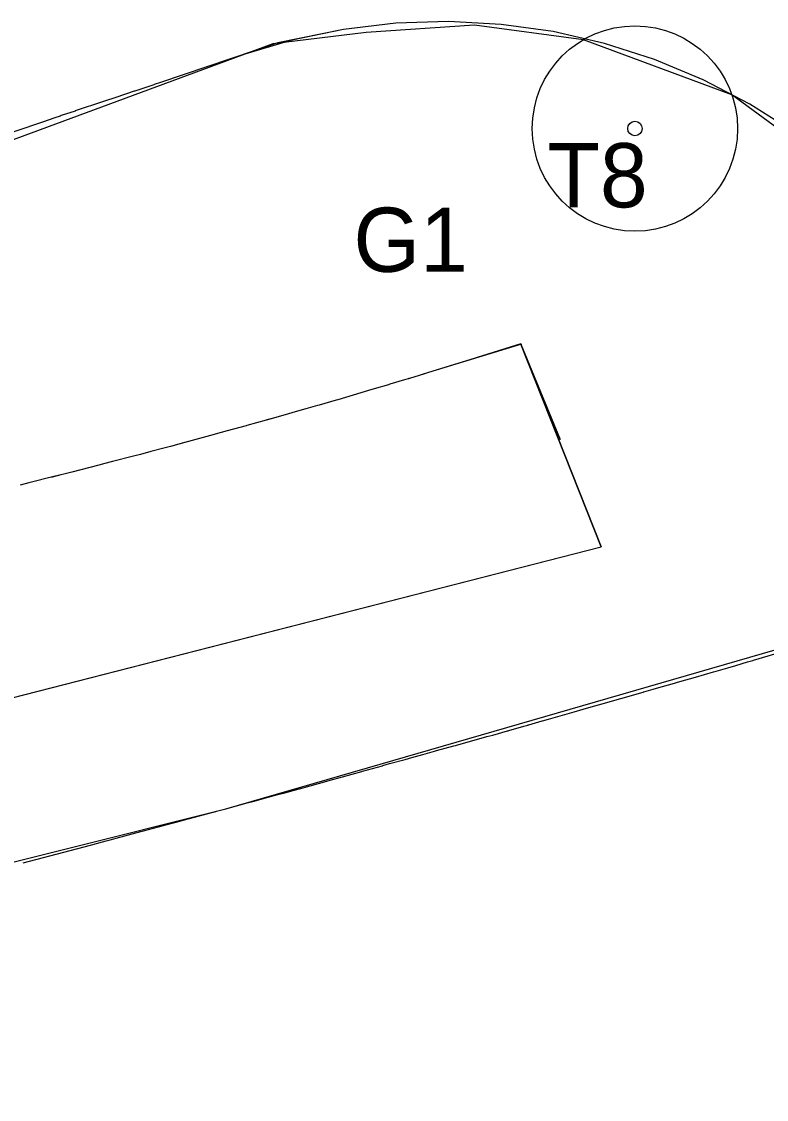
# Model space of a CAD drawing. Extents: x 0 to 512122, y 0 to 6212554.
# Drawn here: x 511665.07 to 511679.58, y 6211767.03 to 6211788.02 of the extents above; entities that cross this region are included whole.
import ezdxf

# ---------------------------------------------------------------- set-up
doc = ezdxf.new("R2010")
doc.units = 0
for name, color, linetype in [('L40 jord udlagt muld og grøft', 7, 'Continuous'), ('Skel', 7, 'Continuous'), ('TV_U_AFM_Symbl_Gul', 7, 'Continuous')]:
    doc.layers.add(name, color=color, linetype=linetype)

# ---------------------------------------------------------------- blocks, each defined once
blk = doc.blocks.new('SOLITAIRE TREES')
at = {"layer": 'Skel'}
for radius in [2, 0.141]:
    blk.add_circle((0, 0), radius, dxfattribs=at)

msp = doc.modelspace()

# ---------------------------------------------------------------- linework, layer by layer
at = {"layer": 'L40 jord udlagt muld og grøft'}
msp.add_line((511651.045, 6211771.305), (511676.359, 6211777.793), dxfattribs=at)
msp.add_lwpolyline([(511684.238, 6211777.086), (511685.25, 6211778.239), (511684.16, 6211780.885), (511682.708, 6211783.396), (511681.248, 6211784.873), (511678.906, 6211786.597), (511676.014, 6211787.668), (511673.894, 6211787.95), (511671.779, 6211787.807), (511669.965, 6211787.585), (511657.374, 6211782.942), (511656.638, 6211783.31), (511651.559, 6211780.896), (511648.87, 6211779.262), (511647.84, 6211778.11), (511646.84, 6211776.718), (511645.839, 6211775.327), (511645.883, 6211772.412), (511646.199, 6211769.278), (511646.437, 6211767.028), (511669.045, 6211772.691)], close=True, dxfattribs=at)
for points in [[(511685.557, 6211777.432), (511684.472, 6211780.286), (511684.067, 6211781.229), (511683.583, 6211782.133), (511683.024, 6211782.992), (511682.393, 6211783.801), (511681.695, 6211784.552), (511680.936, 6211785.242), (511680.121, 6211785.864), (511679.256, 6211786.414), (511678.346, 6211786.889), (511677.4, 6211787.284), (511676.423, 6211787.596), (511675.424, 6211787.825), (511674.408, 6211787.967), (511673.384, 6211788.021), (511672.359, 6211787.989), (511671.34, 6211787.868), (511670.336, 6211787.662), (511669.353, 6211787.37)], [(511685.554, 6211777.44), (511684.472, 6211780.286), (511684.067, 6211781.229), (511683.583, 6211782.133), (511683.024, 6211782.992), (511682.393, 6211783.801), (511681.695, 6211784.552), (511680.936, 6211785.242), (511680.121, 6211785.864), (511679.256, 6211786.414), (511678.346, 6211786.889), (511677.4, 6211787.284), (511676.423, 6211787.596), (511675.424, 6211787.825), (511674.408, 6211787.967), (511673.384, 6211788.021), (511672.359, 6211787.989), (511671.34, 6211787.868), (511670.062, 6211787.605)], [(511670.062, 6211787.605), (511667.775, 6211786.835), (511667.65, 6211786.793), (511667.642, 6211786.79), (511667.277, 6211786.668), (511667.263, 6211786.663), (511666.906, 6211786.544), (511666.68, 6211786.468), (511666.663, 6211786.463), (511666.113, 6211786.28), (511666.109, 6211786.279), (511665.842, 6211786.19), (511665.818, 6211786.181), (511665.718, 6211786.148), (511665.473, 6211786.065), (511665.279, 6211785.999), (511665.15, 6211785.954), (511664.759, 6211785.819)], [(511651.045, 6211771.305), (511676.359, 6211777.793), (511674.796, 6211781.736), (511672.996, 6211781.184), (511672.875, 6211781.147), (511672.816, 6211781.13), (511672.625, 6211781.072), (511672.528, 6211781.042), (511672.241, 6211780.956), (511672.217, 6211780.949), (511671.938, 6211780.866), (511671.825, 6211780.833), (511671.227, 6211780.657), (511671.195, 6211780.648), (511670.867, 6211780.553), (511670.832, 6211780.543), (511670.608, 6211780.478), (511670.396, 6211780.418), (511670.268, 6211780.381), (511669.974, 6211780.298), (511669.836, 6211780.259), (511669.458, 6211780.154), (511669.443, 6211780.149), (511669.073, 6211780.047), (511668.839, 6211779.983), (511668.82, 6211779.978), (511668.25, 6211779.823), (511667.968, 6211779.748), (511667.943, 6211779.741), (511667.839, 6211779.713), (511667.584, 6211779.646), (511667.382, 6211779.592), (511667.246, 6211779.557), (511666.838, 6211779.451), (511666.662, 6211779.405), (511666.572, 6211779.382), (511666.046, 6211779.248), (511665.89, 6211779.208), (511665.835, 6211779.194), (511665.642, 6211779.145), (511665.261, 6211779.049), (511665.211, 6211779.036), (511665.04, 6211778.993)], [(511674.793, 6211781.744), (511673.944, 6211781.476), (511673.806, 6211781.433), (511673.654, 6211781.386), (511673.485, 6211781.334), (511672.996, 6211781.184), (511672.881, 6211781.149), (511672.875, 6211781.147), (511672.816, 6211781.13), (511672.625, 6211781.072), (511672.611, 6211781.067), (511672.605, 6211781.066), (511672.528, 6211781.042), (511672.241, 6211780.956), (511672.228, 6211780.952), (511672.217, 6211780.949), (511671.938, 6211780.866), (511671.825, 6211780.833), (511671.227, 6211780.657), (511671.195, 6211780.648), (511670.867, 6211780.553), (511670.832, 6211780.543), (511670.608, 6211780.478), (511670.396, 6211780.418), (511670.268, 6211780.381), (511669.974, 6211780.298), (511669.844, 6211780.262), (511669.836, 6211780.259), (511669.458, 6211780.154), (511669.443, 6211780.149), (511669.073, 6211780.047), (511668.839, 6211779.983), (511668.82, 6211779.978), (511668.25, 6211779.823), (511668.245, 6211779.822), (511667.968, 6211779.748), (511667.943, 6211779.741), (511667.839, 6211779.713), (511667.584, 6211779.646), (511667.382, 6211779.592), (511667.246, 6211779.557), (511666.838, 6211779.451), (511666.662, 6211779.405), (511666.647, 6211779.401), (511666.572, 6211779.382), (511666.046, 6211779.248), (511665.89, 6211779.208), (511665.835, 6211779.194), (511665.662, 6211779.15), (511665.642, 6211779.145), (511665.261, 6211779.049), (511665.211, 6211779.036), (511665.04, 6211778.993)], [(511674.806, 6211781.739), (511672.996, 6211781.184), (511672.881, 6211781.149), (511672.875, 6211781.147), (511672.816, 6211781.13), (511672.625, 6211781.072), (511672.611, 6211781.067), (511672.605, 6211781.066), (511672.528, 6211781.042), (511672.241, 6211780.956), (511672.228, 6211780.952), (511672.217, 6211780.949), (511671.938, 6211780.866), (511671.825, 6211780.833), (511671.227, 6211780.657), (511671.195, 6211780.648), (511670.867, 6211780.553), (511670.832, 6211780.543), (511670.608, 6211780.478), (511670.396, 6211780.418), (511670.268, 6211780.381), (511669.974, 6211780.298), (511669.844, 6211780.262), (511669.836, 6211780.259), (511669.458, 6211780.154), (511669.443, 6211780.149), (511669.073, 6211780.047), (511668.839, 6211779.983), (511668.82, 6211779.978), (511668.25, 6211779.823), (511668.245, 6211779.822), (511667.968, 6211779.748), (511667.943, 6211779.741), (511667.839, 6211779.713), (511667.584, 6211779.646), (511667.382, 6211779.592), (511667.246, 6211779.557), (511666.838, 6211779.451), (511666.662, 6211779.405), (511666.647, 6211779.401), (511666.572, 6211779.382), (511666.046, 6211779.248), (511665.89, 6211779.208), (511665.835, 6211779.194), (511665.662, 6211779.15), (511665.642, 6211779.145), (511665.261, 6211779.049), (511665.211, 6211779.036), (511665.04, 6211778.993)], [(511674.796, 6211781.736), (511672.996, 6211781.184), (511672.881, 6211781.149), (511672.875, 6211781.147), (511672.816, 6211781.13), (511672.625, 6211781.072), (511672.611, 6211781.067), (511672.605, 6211781.066), (511672.528, 6211781.042), (511672.241, 6211780.956), (511672.228, 6211780.952), (511672.217, 6211780.949), (511671.938, 6211780.866), (511671.825, 6211780.833), (511671.227, 6211780.657), (511671.195, 6211780.648), (511670.867, 6211780.553), (511670.832, 6211780.543), (511670.608, 6211780.478), (511670.396, 6211780.418), (511670.268, 6211780.381), (511669.974, 6211780.298), (511669.844, 6211780.262), (511669.836, 6211780.259), (511669.458, 6211780.154), (511669.443, 6211780.149), (511669.073, 6211780.047), (511668.839, 6211779.983), (511668.82, 6211779.978), (511668.25, 6211779.823), (511668.245, 6211779.822), (511667.968, 6211779.748), (511667.943, 6211779.741), (511667.839, 6211779.713), (511667.584, 6211779.646), (511667.382, 6211779.592), (511667.246, 6211779.557), (511666.838, 6211779.451), (511666.662, 6211779.405), (511666.647, 6211779.401), (511666.572, 6211779.382), (511666.046, 6211779.248), (511665.89, 6211779.208), (511665.835, 6211779.194), (511665.662, 6211779.15), (511665.642, 6211779.145), (511665.261, 6211779.049), (511665.211, 6211779.036), (511665.04, 6211778.993)], [(511674.796, 6211781.736), (511675.561, 6211779.884)], [(511674.796, 6211781.736), (511676.359, 6211777.793)], [(511665.099, 6211771.636), (511666.41, 6211771.98), (511666.455, 6211771.992), (511666.715, 6211772.062), (511666.792, 6211772.083), (511666.982, 6211772.134), (511667.009, 6211772.141), (511667.22, 6211772.198), (511667.393, 6211772.245), (511667.444, 6211772.259), (511667.83, 6211772.363), (511667.851, 6211772.369), (511668.027, 6211772.416), (511668.082, 6211772.431), (511668.241, 6211772.474), (511668.774, 6211772.618), (511668.85, 6211772.639), (511668.866, 6211772.643), (511669.045, 6211772.691), (511669.46, 6211772.803), (511669.597, 6211772.84), (511669.803, 6211772.896), (511670.063, 6211772.966), (511670.169, 6211772.995), (511670.195, 6211773.002), (511670.477, 6211773.078), (511670.482, 6211773.079), (511671.062, 6211773.241), (511671.081, 6211773.246), (511671.319, 6211773.312), (511671.696, 6211773.417), (511671.712, 6211773.421), (511672.098, 6211773.528), (511672.106, 6211773.531), (511672.238, 6211773.568), (511672.538, 6211773.651), (511672.669, 6211773.687), (511672.886, 6211773.748), (511673.115, 6211773.811), (511673.151, 6211773.821), (511673.486, 6211773.915), (511673.519, 6211773.924), (511674.132, 6211774.094), (511674.248, 6211774.126), (511674.534, 6211774.206), (511674.545, 6211774.209), (511674.558, 6211774.213), (511674.852, 6211774.297), (511674.932, 6211774.32), (511674.938, 6211774.321), (511674.952, 6211774.325), (511675.148, 6211774.382), (511675.208, 6211774.399), (511675.215, 6211774.401), (511675.332, 6211774.434), (511675.834, 6211774.578), (511676.008, 6211774.628), (511676.164, 6211774.672), (511676.306, 6211774.713), (511677.179, 6211774.963), (511677.186, 6211774.965), (511677.192, 6211774.967), (511677.375, 6211775.019), (511677.482, 6211775.05), (511677.744, 6211775.124), (511677.89, 6211775.166), (511678.195, 6211775.254), (511678.549, 6211775.355), (511678.599, 6211775.369), (511678.83, 6211775.437), (511678.984, 6211775.482), (511679.21, 6211775.549), (511679.316, 6211775.58), (511679.325, 6211775.583), (511679.787, 6211775.719)]]:
    msp.add_lwpolyline(points, dxfattribs=at)

# ---------------------------------------------------------------- block references
at = {"layer": 'Skel'}
msp.add_blockref('SOLITAIRE TREES', (511677.017, 6211785.938), dxfattribs=at)

# ---------------------------------------------------------------- texts
at = {"layer": 'TV_U_AFM_Symbl_Gul'}
for s, p in [('T8', (511675.315, 6211784.403)), ('G1', (511671.534, 6211783.147))]:
    msp.add_text(s, height=1.25, dxfattribs=at).set_placement(p)

doc.saveas('drawing.dxf')
